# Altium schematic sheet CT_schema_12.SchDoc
size 519 x 434 mm
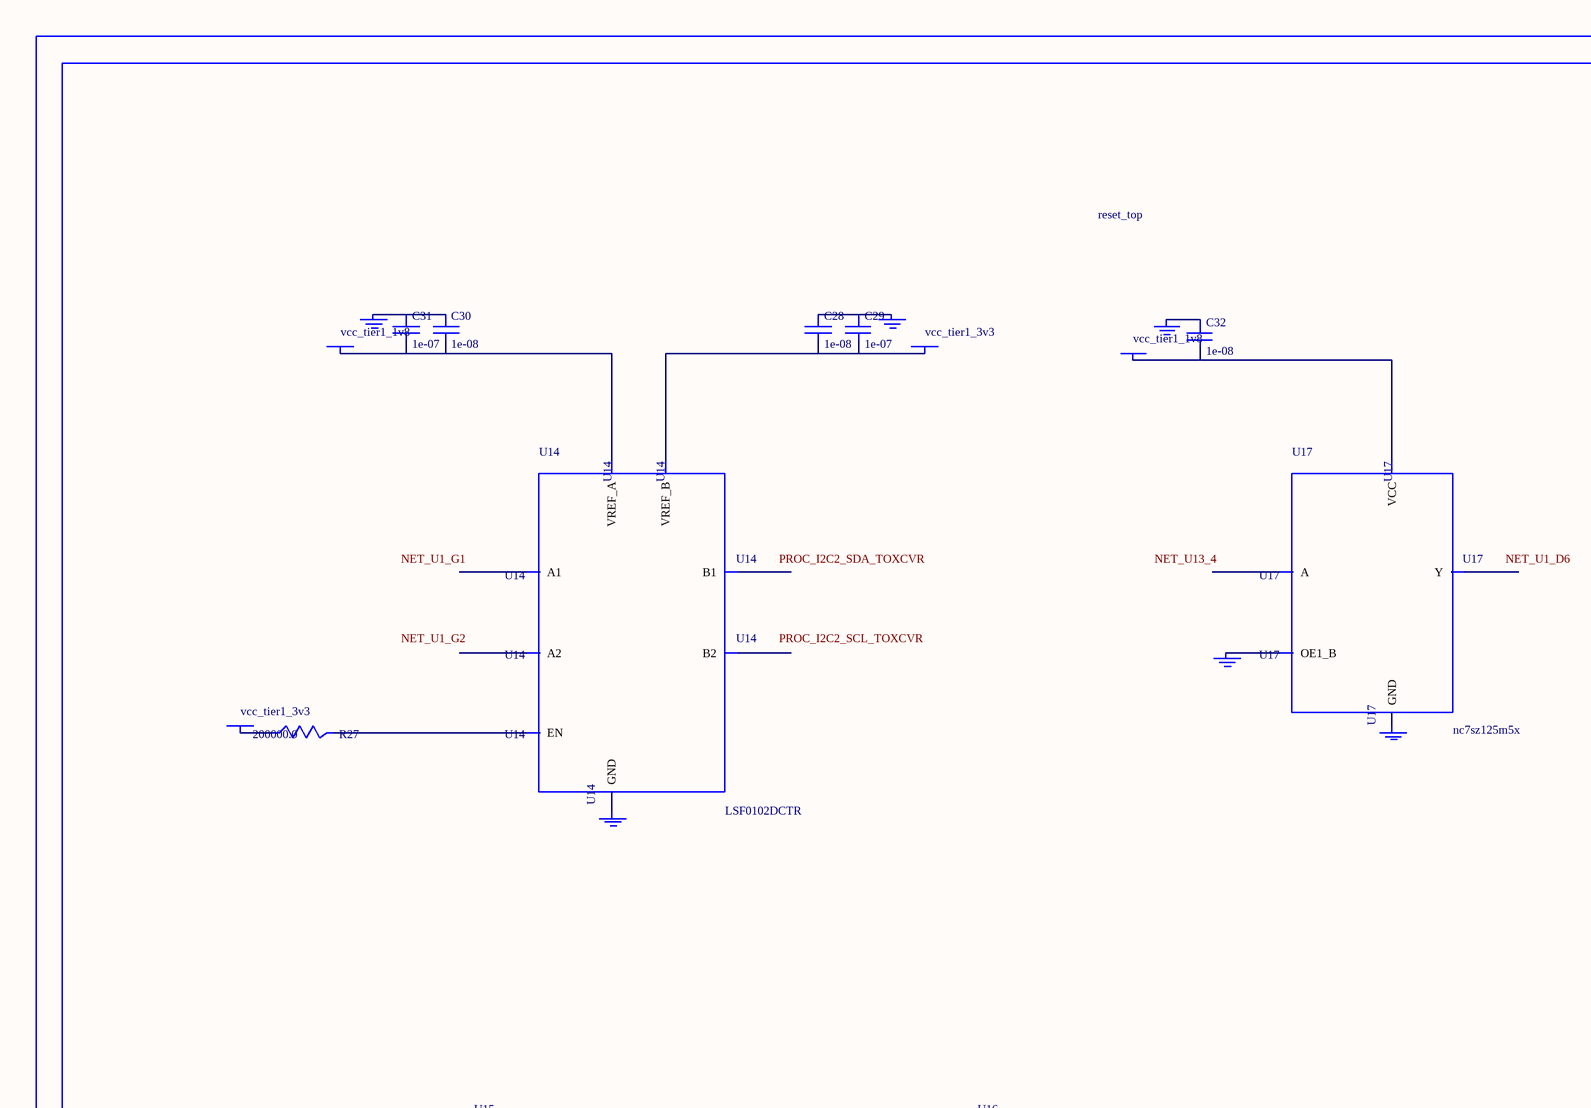
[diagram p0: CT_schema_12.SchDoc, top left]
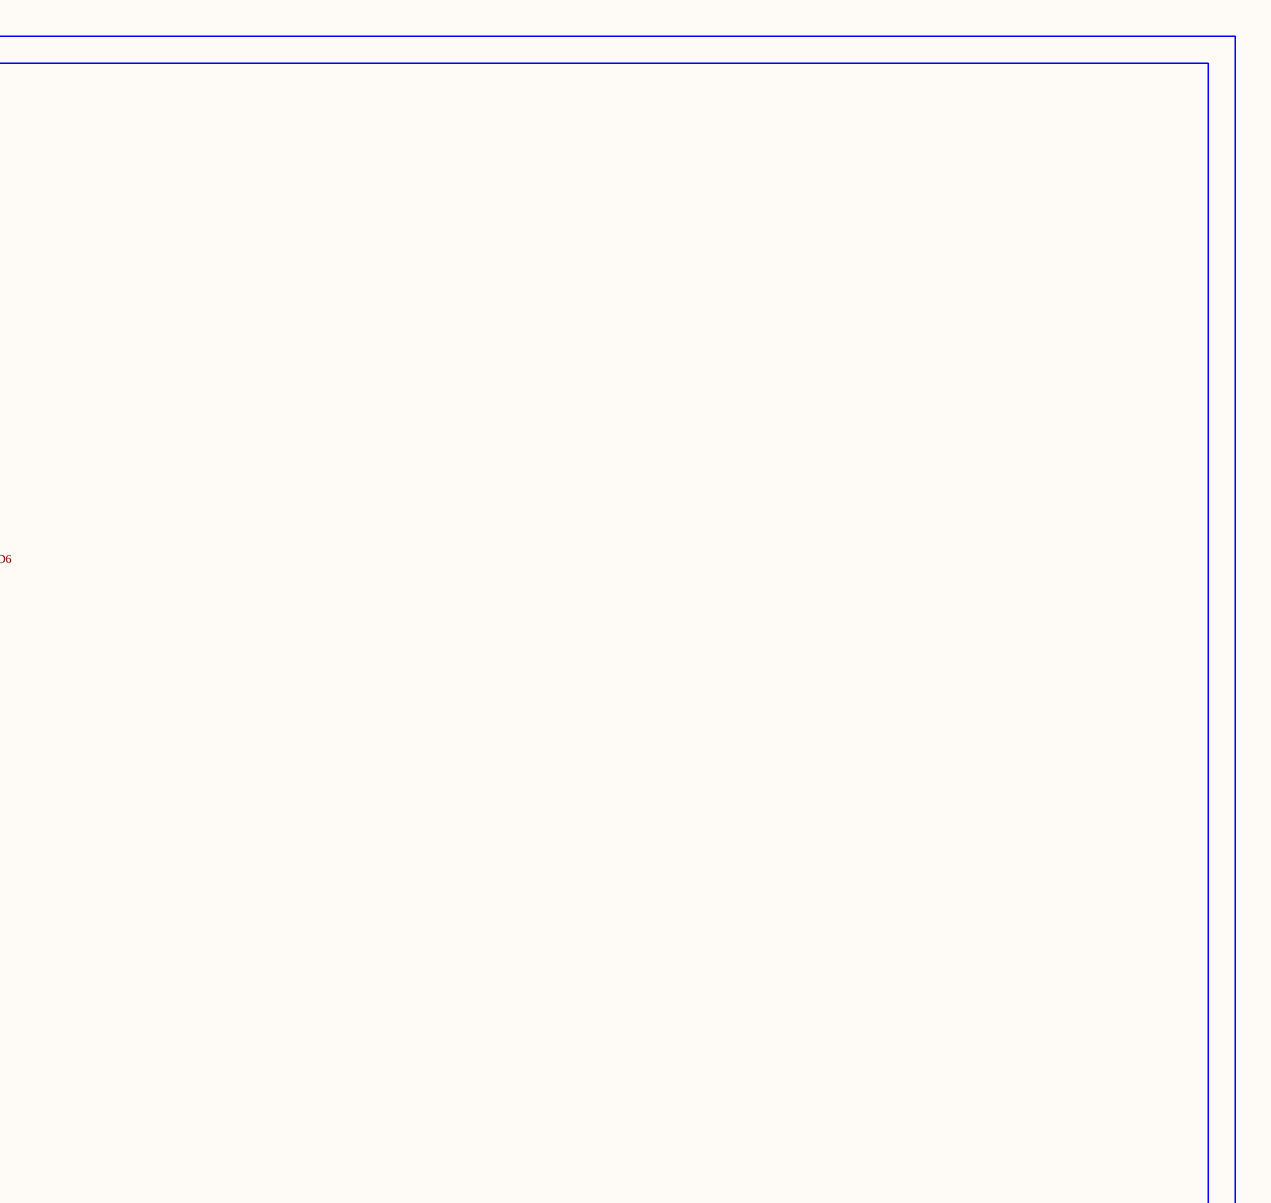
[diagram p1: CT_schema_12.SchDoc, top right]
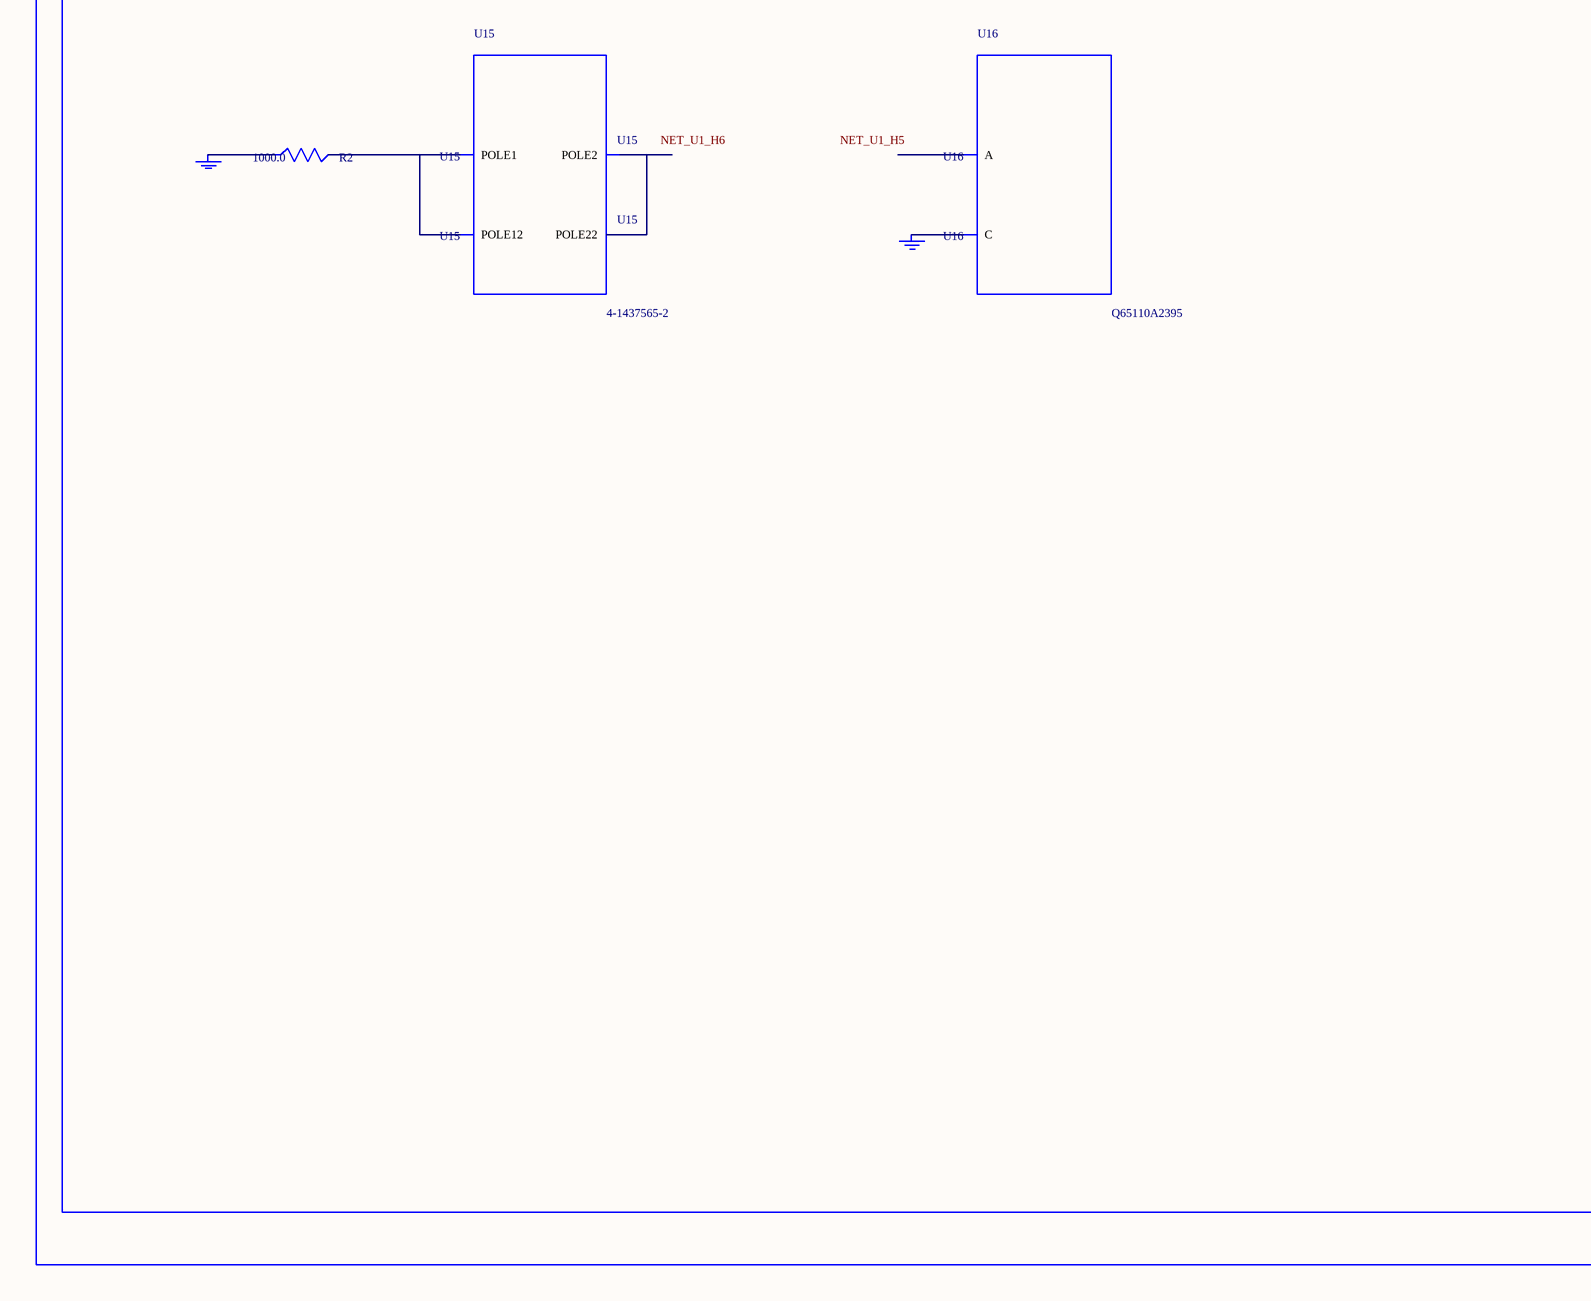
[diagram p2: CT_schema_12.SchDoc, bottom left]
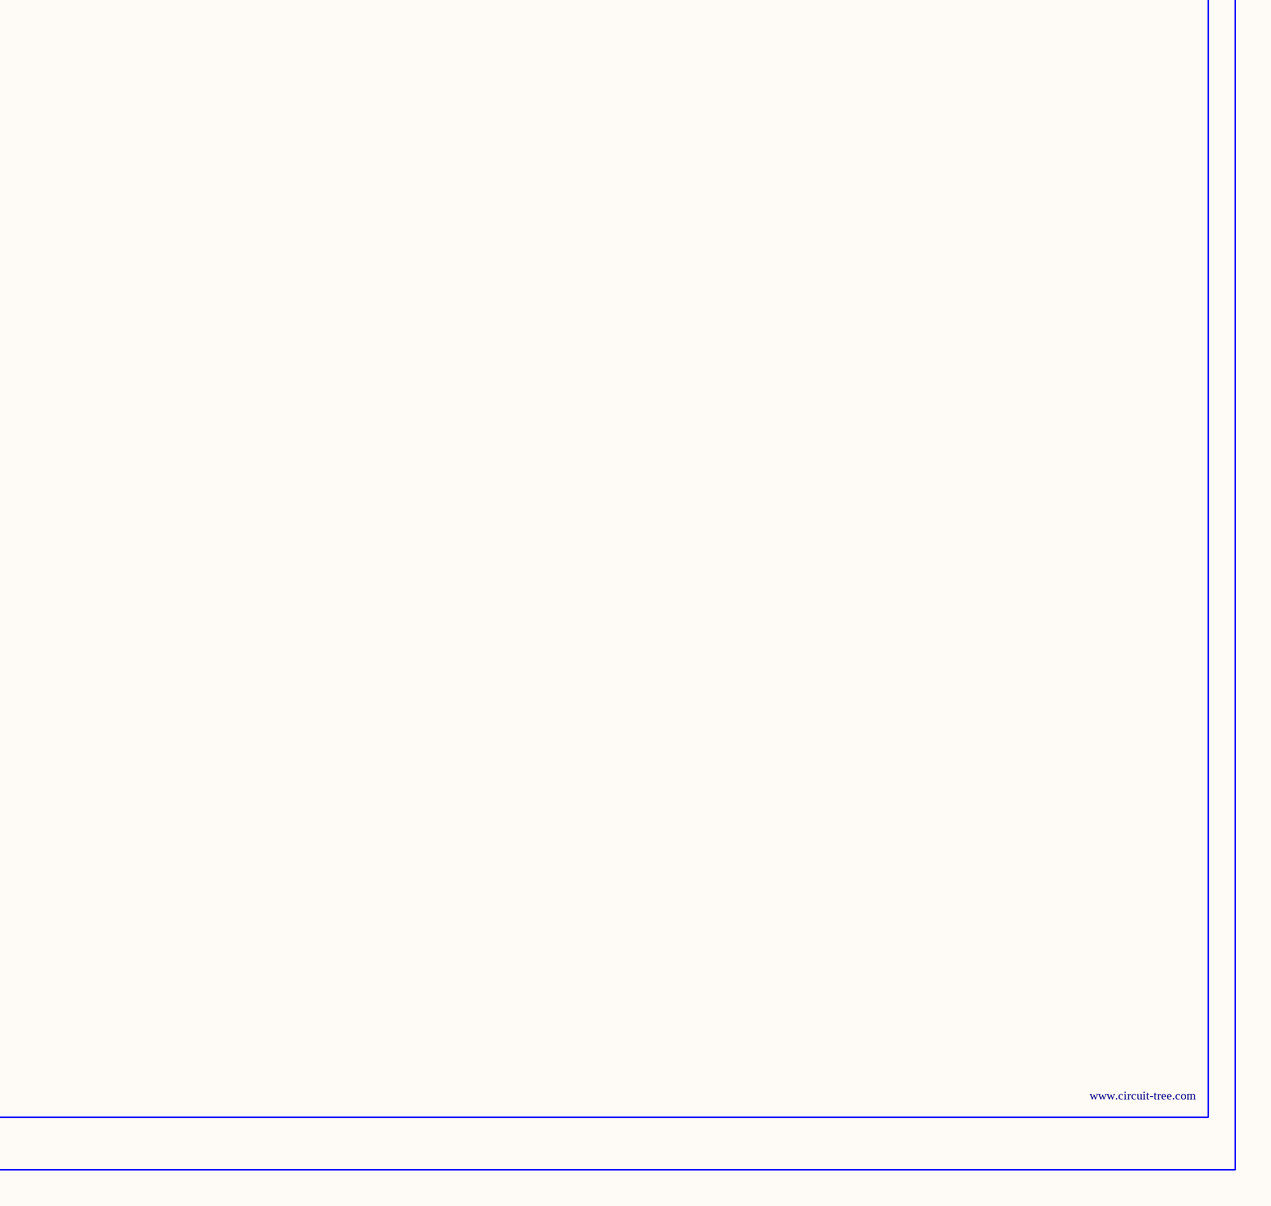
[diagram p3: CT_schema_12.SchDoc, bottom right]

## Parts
BORDER11  (no value)
C28  1e-08  [C0402]
C29  1e-07  [C0402]
C30  1e-08  [C0402]
C31  1e-07  [C0402]
C32  1e-08  [C0402]
GND_INSTANCE_11_0  (no value)
GND_INSTANCE_11_1  (no value)
GND_INSTANCE_11_2  (no value)
GND_INSTANCE_11_3  (no value)
GND_INSTANCE_11_4  (no value)
GND_INSTANCE_11_5  (no value)
GND_INSTANCE_11_6  (no value)
GND_INSTANCE_11_7  (no value)
POWER_INSTANCE_11_0  vcc_tier1_1v8
POWER_INSTANCE_11_1  vcc_tier1_3v3
POWER_INSTANCE_11_2  vcc_tier1_3v3
POWER_INSTANCE_11_3  vcc_tier1_1v8
R2  1000.0  [R0603]
R27  200000.0  [R0603]
U14  LSF0102DCTR  [DCU0008A_N]
U15  4-1437565-2  [SW_4-1437565-2]
U16  Q65110A2395  [LGM67K-G1J2-24-Z]
U17  nc7sz125m5x  [NC7SZ125M5X]

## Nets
NetC28_1: C28.1 C29.1 GND_INSTANCE_11_1.0(GND)
NetC28_2: C28.2 C29.2 POWER_INSTANCE_11_1.0(PWR) U14.7(VREF_B)
NetC30_1: C30.1 C31.1 GND_INSTANCE_11_0.0(GND)
NetC30_2: C30.2 C31.2 POWER_INSTANCE_11_0.0(PWR) U14.2(VREF_A)
NetC32_1: C32.1 GND_INSTANCE_11_5.0(GND)
NetC32_2: C32.2 POWER_INSTANCE_11_3.0(PWR) U17.5(VCC)
NetGND_INSTANCE_11_2_0: GND_INSTANCE_11_2.0(GND) U14.1(GND)
NetGND_INSTANCE_11_3_0: GND_INSTANCE_11_3.0(GND) R2.1
NetGND_INSTANCE_11_4_0: GND_INSTANCE_11_4.0(GND) U16.C
NetGND_INSTANCE_11_6_0: GND_INSTANCE_11_6.0(GND) U17.1(OE1_B)
NetGND_INSTANCE_11_7_0: GND_INSTANCE_11_7.0(GND) U17.3(GND)
NetPOWER_INSTANCE_11_2_0: POWER_INSTANCE_11_2.0(PWR) R27.1
NetR2_2: R2.2 U15.1(POLE1) U15.2(POLE12)
NetR27_2: R27.2 U14.8(EN)
NetU15_3: U15.3(POLE2) U15.4(POLE22)

Not connected (* = marked no-connect by the designer): U14 3(A1) 4(A2) 5(B2) 6(B1); U16 A; U17 2(A) 4(Y)

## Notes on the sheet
- Labels drawn without touching a wire or pin: NET_U1_D6, NET_U1_G1, NET_U1_G2, NET_U1_H5, NET_U1_H6, NET_U13_4, PROC_I2C2_SCL_TOXCVR, PROC_I2C2_SDA_TOXCVR

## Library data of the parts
BORDER11 = BORDER_PAGE11
C28 C30 C32 = C0402C103K3RAC
C29 C31 = C0402C104K3RACTU
GND_INSTANCE_11_0-GND_INSTANCE_11_7 = GND
POWER_INSTANCE_11_0-POWER_INSTANCE_11_3 = PWR
R2 = RC0603JR-071KL
R27 = RC0603JR-07200KL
